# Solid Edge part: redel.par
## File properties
Author: Mac
Template: Normal.par
Last saved by: Mac
Revision: 2
Application: Solid Edge
Density: 631,000 kg/m^3
Accuracy: 0,990
Material: Wood, Oak
Face Style: Tan
Fill Style: Cork
Virtual Style: Teak
Coef. of Thermal Exp: 0.0
Thermal Conductivity: 0.0
Specific Heat: 0.0
Modulus of Elasticity: 0.0
Poission's Ratio: 0.0
Yield Stress: 0.0
Ultimate Stress: 0.0
Elongation: 0.0
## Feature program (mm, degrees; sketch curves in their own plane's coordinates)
sketch for "ExtrudedProtrusion_2" plane through (0, 0, 39.6) normal (0, 0, 1) x-axis (1, 0, 0)
  line (-0.6, 0.25) -> (0, 0.25)
  line (0, 0.25) -> (0, -0.25)
  line (-0.6, -0.25) -> (0, -0.25)
  line (-0.6, -0.21) -> (-0.6, -0.25)
  line (-0.6, -0.21) -> (-0.04, -0.21)
  line (-0.04, 0.21) -> (-0.04, -0.21)
  line (-0.6, 0.21) -> (-0.04, 0.21)
  line (-0.6, 0.25) -> (-0.6, 0.21)
extrude "ExtrudedProtrusion_2" add finite 0.8 along -normal  Profile_Plane1_Distance = 39.6 mm
sketch for "unnamed Cutout 1" plane through (-0.3, -0.25, 38.3) normal (0, -1, 0) x-axis (1, 0, 0)
  arc centre (0.3, 0.65) radius 0.65 from (0.3, 1.3) to (-0.2233, 1.0355) ccw
  arc centre (-0.0394, 0.9) radius 0.2285 from (-0.2233, 1.0355) to (-0.2233, 0.7645) ccw
  arc centre (0.3, 1.15) radius 0.65 from (0.3, 0.5) to (-0.2233, 0.7645) cw
extrude "unnamed Cutout 1" cut through along -normal
swept protrusion "unnamed SweptProtrusion 1"
body pattern "unnamed BodyPattern 1"
pattern "unnamed Pattern 1"
sketch for "ExtrudedProtrusion_3" plane through (0, 0, 35.3) normal (0, 0, 1) x-axis (1, 0, 0)
  line (-3.8, 8) -> (-3.2865, 8)
  arc centre (-3.2865, 7.7) radius 0.3 from (-3.2865, 8) to (-2.9865, 7.7) cw
  line (-2.9865, 7.7) -> (-2.9865, 0.3)
  arc centre (-3.2865, 0.3) radius 0.3 from (-2.9865, 0.3) to (-3.2865, 0) cw
  line (-3.2865, 0) -> (-3.8, 0)
  line (-4.2, 0) -> (-4.7074, 0)
  arc centre (-4.7074, 0.3) radius 0.3 from (-4.7074, 0) to (-5.0074, 0.3) cw
  line (-5.0074, 0.3) -> (-5.0074, 7.7)
  arc centre (-4.7074, 7.7) radius 0.3 from (-4.7074, 8) to (-5.0074, 7.7) ccw
  line (-4.7074, 8) -> (-4.2, 8)
extrude "ExtrudedProtrusion_3" add finite 0.4 along -normal
pattern "Pattern_2" of "ExtrudedProtrusion_3" along a curve  XDirCount = 9; YDirCount = 6
extrude "unnamed Protrusion 1" add finite 0.4
extrude "unnamed Protrusion 2" add finite 0.4
extrude "unnamed Protrusion 3" add finite 0.4
extrude "unnamed Protrusion 4" add finite 0.4
extrude "unnamed Protrusion 5" add finite 0.4
extrude "unnamed Protrusion 6" add finite 0.4
extrude "unnamed Protrusion 7" add finite 0.4
extrude "unnamed Protrusion 8" add finite 0.4
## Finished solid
Body 1: solid body, 122 faces, 342 edges, 224 vertices.
  Faces by surface: plane 78, cylinder 42, torus 2
  Edges by curve: line 216, circle 124, intersection 2
Bounding box of the edges (mm; curved faces can reach further): 5.007 x 8.500 x 39.600, from (-5.0074, -0.25, 0) to (0, 8.25, 39.6).
Cylindrical faces by radius (mm): R0.2 x2, R0.2285 x4, R0.3 x32, R0.65 x4
Toroidal faces (ring radius, tube radius in mm): R4 r0.2 x2
Planar faces by outward normal: +x 10, +y 20, +z 8, -x 10, -y 20, -z 10
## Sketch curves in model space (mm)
arc centre (0, 0, 35.3) radius 4 from (0, 0, 39.3) through (-3.2086, 0, 37.6884) to (-3.8921, 0, 34.3771)
line (0, 0, 0) -> (-0.8, 0, 0)
line (-4, 0, 35.3) -> (-4, 0, 0)
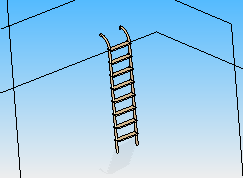
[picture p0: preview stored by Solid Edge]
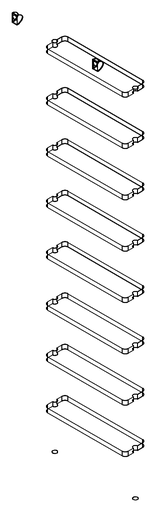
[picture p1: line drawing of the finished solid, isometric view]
